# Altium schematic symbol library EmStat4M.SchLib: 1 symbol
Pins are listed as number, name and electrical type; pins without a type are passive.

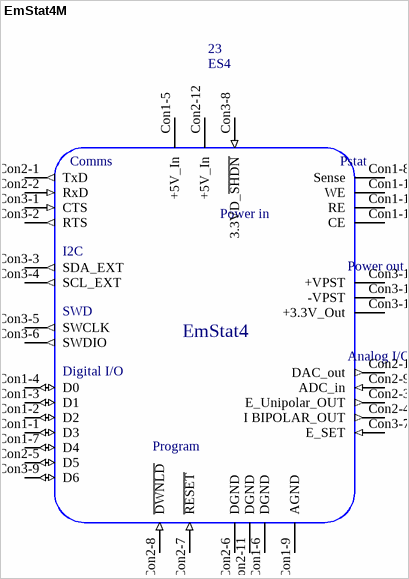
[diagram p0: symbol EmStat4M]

## EmStat4M
designator 23, comment ES4
footprint Emstat4_V1.0
pins: Con1-1 D3 (io), Con1-2 D2 (io), Con1-3 D1 (io), Con1-4 D0 (io), Con1-5 +5V_In (power), Con1-6 DGND (power), Con1-7 D4 (io), Con1-8 Sense (hiz), Con1-9 AGND (power), Con1-10 WE, Con1-11 RE (hiz), Con1-12 CE, Con2-1 TxD (out), Con2-2 RxD (in), Con2-3 E_Unipolar_OUT (out), Con2-4 I BIPOLAR_OUT (out), Con2-5 D5 (io), Con2-6 DGND (power), Con2-7 ~{RESET} (in), Con2-8 ~{DWNLD} (in), Con2-9 ADC_in (in), Con2-10 DAC_out (out), Con2-11 DGND (power), Con2-12 +5V_In (power), Con3-1 CTS (in), Con3-2 RTS (out), Con3-3 SDA_EXT (out), Con3-4 SCL_EXT (out), Con3-5 SWCLK (out), Con3-6 SWDIO (out), Con3-7 E_SET (in), Con3-8 3.3VD_~{SHDN} (in), Con3-9 D6 (io), Con3-10 +3.3V_Out (power), Con3-11 -VPST (power), Con3-12 +VPST (power)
